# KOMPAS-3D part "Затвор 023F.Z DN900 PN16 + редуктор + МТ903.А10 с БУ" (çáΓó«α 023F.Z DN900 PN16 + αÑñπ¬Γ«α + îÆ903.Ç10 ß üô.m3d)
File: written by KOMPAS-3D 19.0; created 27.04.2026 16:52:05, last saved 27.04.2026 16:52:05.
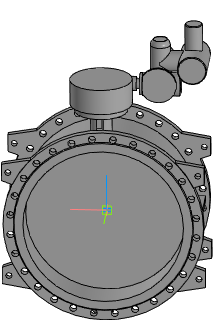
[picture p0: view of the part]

Document properties: Полное имя файла: ..\..\Затвор 023F.Z DN400-DN1600 + редуктор + МТ903\Затвор 023F.Z DN900 PN16 + редуктор + МТ903.А10 с БУ.a3d

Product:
- Part/product: Затвор 023F.Z DN900 PN16 + редуктор + МТ903.А10 с БУ
    Масса: 1184.73

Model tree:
1. Операция без истории:1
